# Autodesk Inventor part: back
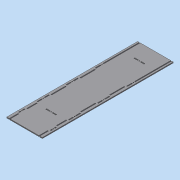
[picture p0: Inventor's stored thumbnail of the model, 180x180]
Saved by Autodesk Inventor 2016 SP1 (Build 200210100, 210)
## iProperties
Created: 2016-06
Part Number: back
Material: Generic
Document SubType Name: Modeling
Designer: Mohamed A.
Density: 1 g/cm^3
Appearance: Default
Author: Mohamed A.
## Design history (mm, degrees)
sketch "Sketch1"
  geometry: L1 (-57, 160)-(57, 160); L2 (57, 160)-(57, -160); L3 (57, -160)-(-57, -160); L4 (-57, -160)-(-57, 160); L5 (-57, 160)-(57, -160); L6 (57, 160)-(-57, -160); 1 further point
  constraints: 12 end point, 2 midpoint, 2 parallel, 1 horizontal, 1 perpendicular
  dimensions: "d0" = 114 distance of L2.end L3.end; "d1" = 320 distance of L1.end L2.end
extrude "Extrusion1" new body sketch "Sketch1" distance "d2" = 3; taper "d3" = 0 deg
sketch "Sketch2"
  geometry: L1 (52, 140.75)-(52, 137.65) reference; L2 (52, 140.75)-(49, 140.75) reference; L3 (49, 137.65)-(49, 140.75) reference; L4 (52, 137.65)-(49, 137.65) reference; L5 (52, 45.05)-(52, 41.95) reference; L6 (52, 45.05)-(49, 45.05) reference; L7 (49, 41.95)-(49, 45.05) reference; L8 (52, 41.95)-(49, 41.95) reference; L9 (-49, 45.05)-(-49, 41.95) reference; L10 (-49, 45.05)-(-52, 45.05) reference; L11 (-52, 41.95)-(-52, 45.05) reference; L12 (-49, 41.95)-(-52, 41.95) reference; L13 (-49, 140.75)-(-49, 137.65) reference; L14 (-49, 140.75)-(-52, 140.75) reference; L15 (-52, 137.65)-(-52, 140.75) reference; L16 (-49, 137.65)-(-52, 137.65) reference; L17 (52, -48.15)-(52, -51.25) reference; L18 (52, -48.15)-(49, -48.15) reference; L19 (49, -51.25)-(49, -48.15) reference; L20 (52, -51.25)-(49, -51.25) reference; L21 (-49, -48.15)-(-49, -51.25) reference; L22 (-49, -48.15)-(-52, -48.15) reference; L23 (-52, -51.25)-(-52, -48.15) reference; L24 (-49, -51.25)-(-52, -51.25) reference; L25 (52, -116.45)-(52, -119.55) reference; L26 (52, -116.45)-(49, -116.45) reference; L27 (49, -119.55)-(49, -116.45) reference; L28 (52, -119.55)-(49, -119.55) reference; L29 (-49, -116.45)-(-49, -119.55) reference; L30 (-49, -116.45)-(-52, -116.45) reference; L31 (-52, -119.55)-(-52, -116.45) reference; L32 (-49, -119.55)-(-52, -119.55) reference; L33 (-49, -114.25)-(-52, -114.25) reference; L34 (-52, -114.25)-(-52, -109) reference; L35 (-52, -109)-(-49, -109) reference; L36 (-49, -109)-(-49, -114.25) reference; L37 (-52, -121.75)-(-49, -121.75) reference; L38 (-49, -121.75)-(-49, -127) reference; L39 (-49, -127)-(-52, -127) reference; L40 (-52, -127)-(-52, -121.75) reference; L41 (-52, 39)-(-49, 39) reference; L42 (-49, 39)-(-49, 25.2) reference; L43 (-49, 25.2)-(-52, 25.2) reference; L44 (-52, 25.2)-(-52, 39) reference; L45 (-49, 48)-(-52, 48) reference; L46 (-52, 48)-(-52, 61.8) reference; L47 (-52, 61.8)-(-49, 61.8) reference; L48 (-49, 61.8)-(-49, 48) reference; L49 (-52, 134.7)-(-49, 134.7) reference; L50 (-49, 134.7)-(-49, 118.4) reference; L51 (-49, 118.4)-(-52, 118.4) reference; L52 (-52, 118.4)-(-52, 134.7) reference; L53 (-49, 143.7)-(-52, 143.7) reference; L54 (-52, 143.7)-(-52, 160) reference; L55 (-52, 160)-(-49, 160) reference; L56 (-49, 160)-(-49, 143.7) reference; L57 (-52, -54.2)-(-49, -54.2) reference; L58 (-49, -54.2)-(-49, -68) reference; L59 (-49, -68)-(-52, -68) reference; L60 (-52, -68)-(-52, -54.2) reference; L61 (-49, -45.2)-(-52, -45.2) reference; L62 (-52, -45.2)-(-52, -31.4) reference; L63 (-52, -31.4)-(-49, -31.4) reference; L64 (-49, -31.4)-(-49, -45.2) reference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; C1 r 1.4 at (50.5, 139.2); C2 r 1.4 at (-50.5, 139.2); C3 r 1.4 at (-50.5, 43.5); C4 r 1.4 at (50.5, 43.5); C5 r 1.4 at (50.5, -49.7); C6 r 1.4 at (-50.5, -49.7); C7 r 1.4 at (50.5, -118); C8 r 1.4 at (-50.5, -118); C9 r 1.4 at (0, 128.5); C10 r 1.4 at (0, -74.5)
  constraints: 224 end point, 56 horizontal, 56 vertical, 10 centre point, 112 other
  dimensions: "d10" = 2.8 diameter of C1; "d11" = 2.8 diameter of C2; "d12" = 2.8 diameter of C3; "d13" = 2.8 diameter of C4; "d14" = 2.8 diameter of C5; "d15" = 2.8 diameter of C6; "d16" = 2.8 diameter of C7; "d17" = 2.8 diameter of C8; "d18" = 2.8 diameter of C9; "d19" = 2.8 diameter of C10; "d20" = 40.66667 distance between parallel lines of L153 L139 (derived); "d21" = 11.83333 distance between parallel lines of L139 L137 (derived); "d22" = 9 distance between parallel lines of L137 L143 (derived); "d23" = 11.83333 distance between parallel lines of L143 L141 (derived); "d24" = 30 distance between parallel lines of L154 L140 (derived)
extrude "Extrusion2" cut sketch "Sketch2" distance "d8" = 10; taper "d9" = 0 deg
sketch "Sketch3"
  geometry: L1 (98, -3)-(98, 0) reference; L2 (0, 0)-(98, 0) reference; L3 (0, 0)-(0, -3) reference; L4 (98, -3)-(0, -3) reference; L5 (-3, -3)-(-3, 0) reference; L6 (-8, 0)-(-3, 0) reference; L7 (-8, 0)-(-8, -3) reference; L8 (-3, -3)-(-8, -3) reference; L9 (101, 0)-(101, -3) reference; L10 (106, -3)-(101, -3) reference; L11 (106, 0)-(106, -3) reference; L12 (101, 0)-(106, 0) reference; 1 further point
extrude "Extrusion3" join sketch "Sketch3" distance "d25" = 100; taper "d26" = 0 deg
sketch "Sketch4"
  geometry: L1 (16.333, 210)-(4.5, 210); L2 (4.5, 210)-(4.5, 207); L3 (4.5, 207)-(16.333, 207); L4 (16.333, 207)-(16.333, 210); L5 (-4.5, 210)-(-16.333, 210); L6 (-16.333, 210)-(-16.333, 207); L7 (-16.333, 207)-(-4.5, 207); L8 (-4.5, 207)-(-4.5, 210); L9 (-57, 260)-(-57, -160) reference; L10 (-49, 260)-(49, 260) reference; L11 (4.5, 210)-(-4.5, 207); L12 (4.5, 207)-(-4.5, 210); C1 r 1.4 at (0, 208.5); 1 further point
  constraints: 20 end point, 4 parallel, 2 horizontal, 2 perpendicular, 1 centre point, 1 midpoint, 1 point on line
  dimensions: "d27" = 11.833 distance of L3.end L2.end; "d28" = 3 distance of L2.end L1.end; "d29" = 11.833 distance of L7.end L6.end; "d30" = 3 distance of L6.end L5.end; "d31" = 9 distance between parallel lines of L8 L2; "d32" = 40.667 distance between parallel lines of L9 L6; "d33" = 50 distance between parallel lines of L10 L5; "d34" = 2.8 diameter of C1
extrude "Extrusion4" cut sketch "Sketch4" distance "d35" = 100; taper "d36" = 0 deg
body "Solid1"
node "Reference6"
node "Reference7"
node "Reference8"
node "Reference9"
node "Reference10"
node "Reference11"
node "Reference12"
node "Reference13"
node "Reference14"
node "Reference15"
node "Projected Loop1"
node "Projected Loop2"
node "Projected Loop3"
